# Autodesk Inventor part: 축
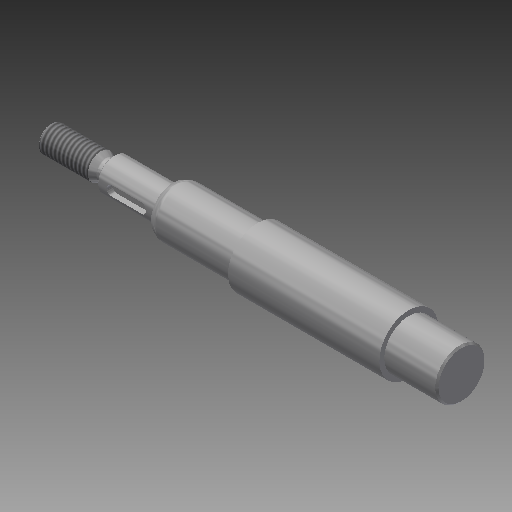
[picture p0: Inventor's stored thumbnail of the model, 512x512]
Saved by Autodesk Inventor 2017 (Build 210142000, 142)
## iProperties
Created: 2015-11
Part Number: 축
Material: 강철, 연강
Document SubType Name: Modeling
Designer: mduedu
Density: 1 g/cm^3
Appearance: 강철
Author: mduedu
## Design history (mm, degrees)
sketch "스케치1"
  geometry: L1 (-86, 0)-(86, 0); L2 (-86, 0)-(-86, 4); L3 (-86, 4)-(-70.732, 4); L4 (-70.732, 4)-(-69, 3); L5 (-69, 3)-(-67, 3); L6 (-67, 3)-(-67, 5); L7 (-67, 5)-(-49, 5); L8 (-49, 5)-(-49, 6.55); L9 (-47.355, 7.5)-(-23, 7.5); L10 (-23, 7.5)-(-23, 9); L11 (0, 0)-(0, 9); L12 (86, 4)-(70.732, 4); L13 (70.732, 4)-(69, 3); L14 (69, 3)-(67, 3); L15 (67, 3)-(67, 5); L16 (67, 5)-(49, 5); L17 (23, 7.5)-(23, 9); L18 (86, 0)-(86, 4); L19 (-23, 9)-(23, 9); L20 (-49, 6.55)-(-47.355, 7.5); L21 (47.355, 7.5)-(23, 7.5); L22 (49, 6.55)-(47.355, 7.5); L23 (49, 5)-(49, 6.55); 1 further point
  constraints: 46 end point, 10 symmetric about line, 6 perpendicular, 5 parallel, 2 midpoint, 1 coincident, 1 horizontal
  dimensions: "d0" = 172 distance of L1.start L1.end (derived); "d1" = 8 diameter of L3 L1; "d2" = 30 deg angle of L4 L5; "d3" = 6 diameter of L5 L1; "d4" = 10 diameter of L7 L1; "d5" = 15 diameter of L9 L1; "d6" = 18 diameter of L19 L1; "d8" = 18 distance of L6.end L7.end; "d9" = 46 distance of L10.end L17.end; "d10" = 2 distance of L4.end L5.end; "d11" = 17 distance from line of L4.end L2; "d16" = 13.1 diameter of L8.end L1; "d17" = 30 deg angle of L20 L9; "d18" = 26 distance between parallel lines of L10 L8
revolve "회전1" sketch "스케치1" stored, may be unused: angle "d12" = 90 deg
chamfer "모따기1" distance "d13" = 0.5; stored, may be unused: second distance "d14" = 2, angle "d15" = 45 deg
fillet "모깎기1" dims "d19" = 4, "d20" = 0.5
node "작업 평면1"
sketch "스케치2" dims "d23" = 12
  geometry: L1 (-4.5, 1.5)-(4.5, 1.5); L2 (4.5, 1.5)-(4.5, -1.5); L3 (4.5, -1.5)-(-4.5, -1.5); L4 (-4.5, -1.5)-(-4.5, 1.5); L5 (-9, -4.5)-(-9, 4.5) reference; 3 further points
  constraints: 8 end point, 2 midpoint, 2 parallel, 2 vertical alignment, 1 horizontal, 1 perpendicular, 4 other
  dimensions: "d21" = 3 distance between parallel lines of L3 L1; "d24" = 3 dimension on L5
extrude "돌출1" cut sketch "스케치2" distance "d25" = 1.8; taper "d26" = 0 deg
feature "스레드1" dims "d27" = 10, "d28" = 0
feature "스레드2" dims "d29" = 10, "d30" = 0
chamfer "모따기2" distance "d31" = 0.5; stored, may be unused: second distance "d32" = 2, angle "d33" = 45 deg
node "작업 평면2"
sketch "스케치3"
  geometry: C1 r 7.5 at (0, 0) reference; 1 further point
extrude "돌출2" cut sketch "스케치3" stored distance "d36" = 10; taper "d37" = 0 deg
chamfer "모따기3" distance "d38" = 0.5; stored, may be unused: second distance "d39" = 2, angle "d40" = 45 deg
fillet "모깎기3" dims "d41" = 0.6
node "솔리드1"
mirror "대칭1"
node "절단 모서리 투영1"
other parameters: "d35" = 16
